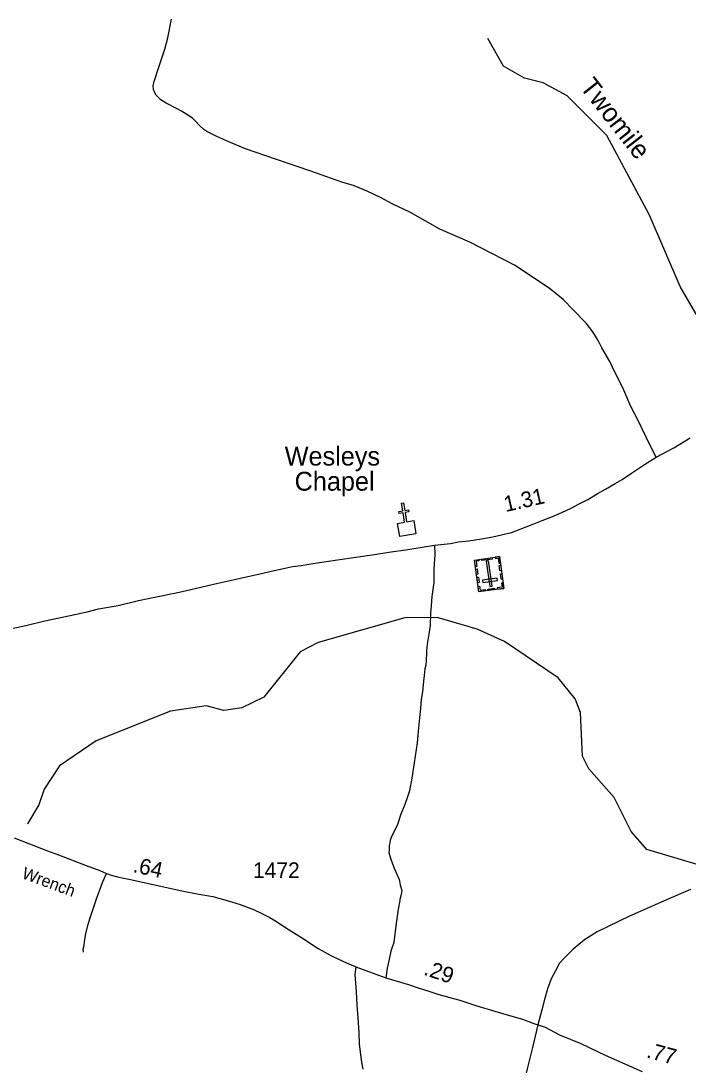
# Model space of a CAD drawing. Extents: x 2093524 to 2270757, y 289120 to 570408.
# Drawn here: x 2127083 to 2132387, y 512508 to 520807 of the extents above; entities that cross this region are included whole.
import ezdxf

# ---------------------------------------------------------------- set-up
doc = ezdxf.new("R2010")
doc.units = 0
for name, color, linetype in [('Exist Cultural Cemetery CELL', 7, 'Continuous'), ('Exist Cultural Church CELL', 7, 'Continuous'), ('Exist Cultural Church Label', 7, 'Continuous'), ('Exist Hydrographic Creek Single Shore', 7, 'Continuous'), ('Exist Hydrographic Misc Water Feature', 7, 'Continuous'), ('Exist Hydrographic Swamp Label', 7, 'Continuous'), ('Exist Road Non-System Type 51', 7, 'Continuous'), ('Exist Road Primary US Attributed', 7, 'Continuous'), ('Exist Road Primary US Mileage Hundredths English Label', 7, 'Continuous'), ('Exist Road Secondary Mileage Hundredths English Label', 7, 'Continuous'), ('Exist Road Secondary Type 51 Attributed', 7, 'Continuous'), ('Exist Road Secondary Type 51 Label', 7, 'Continuous'), ('Exist Road Secondary Type 51 Number Label', 7, 'Continuous')]:
    doc.layers.add(name, color=color, linetype=linetype)

msp = doc.modelspace()

# ---------------------------------------------------------------- linework, layer by layer
at = {"layer": 'Exist Cultural Cemetery CELL'}
for points in [[(2130921.8, 516297.1), (2130724.6, 516269.6), (2130689.4, 516521.8), (2130886.6, 516549.3)], [(2130722.2, 516526.3), (2130723.8, 516515), (2130702, 516511.9), (2130707.6, 516471.9), (2130696.6, 516470.4), (2130689.4, 516521.8)], [(2130831.3, 516530), (2130747.2, 516518.2), (2130745.7, 516529.5), (2130829.7, 516541.3)], [(2130853.8, 516544.7), (2130855.4, 516533.3), (2130877.2, 516536.3), (2130882.8, 516496.3), (2130893.8, 516497.8), (2130886.7, 516549.2)], [(2130710.7, 516451.8), (2130716.7, 516408.9), (2130705.4, 516407.3), (2130699.4, 516450.2)], [(2130809.8, 516311.1), (2130828.3, 516313.6), (2130800.2, 516514.5), (2130781.7, 516511.9)], [(2130896.3, 516480), (2130902.3, 516437.1), (2130891, 516435.6), (2130885, 516478.4)], [(2130719.8, 516386.5), (2130725.7, 516343.6), (2130714.5, 516342), (2130708.5, 516384.9)], [(2130872, 516358.9), (2130869.4, 516377.4), (2130752.8, 516361.1), (2130755.3, 516342.6)], [(2130905.6, 516413.4), (2130911.6, 516370.6), (2130900.3, 516369), (2130894.3, 516411.9)], [(2130718.5, 516312.5), (2130729.8, 516314.1), (2130734.2, 516282.2), (2130774.4, 516287.8), (2130775.9, 516276.8), (2130724.5, 516269.6)], [(2130848.4, 516286.9), (2130797.1, 516279.7), (2130795.5, 516291), (2130846.9, 516298.2)], [(2130915.8, 516340), (2130904.6, 516338.4), (2130909, 516306.5), (2130868.8, 516301), (2130870.4, 516289.9), (2130921.8, 516297.1)]]:
    msp.add_lwpolyline(points, close=True, dxfattribs=at)
at = {"layer": 'Exist Cultural Church CELL'}
msp.add_lwpolyline([(2130077.4, 516813.3), (2130133.5, 516822.8), (2130120.9, 516897.9), (2130089.3, 516892.6), (2130086.7, 516908.4), (2130118.2, 516913.7), (2130108.2, 516973), (2130124, 516975.6), (2130134, 516916.3), (2130165.6, 516921.6), (2130168.2, 516905.9), (2130136.7, 516900.6), (2130149.3, 516825.5), (2130206.2, 516835), (2130223.8, 516730), (2130095, 516708.3)], close=True, dxfattribs=at)
at = {"layer": 'Exist Hydrographic Creek Single Shore'}
msp.add_lwpolyline([(2132885.3, 513974.6), (2132951.4, 514235.7), (2133247.5, 514935.1), (2133246.4, 515309), (2133134.3, 516108.5), (2133175.3, 516274.9), (2133179.4, 517150.7), (2133069.3, 517566.2), (2132859.3, 517957.6), (2132449.4, 518480.9), (2132323.3, 518696.6), (2132079.3, 519262.4), (2131740.8, 519896), (2131425.2, 520211.8), (2131234.4, 520314.6), (2131087.6, 520351.3), (2130918.8, 520446.8), (2130794, 520667.1)], dxfattribs=at)
at = {"layer": 'Exist Hydrographic Misc Water Feature'}
msp.add_lwpolyline([(2132885.3, 513974.6), (2132059.4, 514220.8), (2131934.3, 514364.4), (2131799.4, 514636.1), (2131598.2, 514863.2), (2131548.4, 514962.6), (2131530.3, 515310.8), (2131488.3, 515419.8), (2131354.2, 515586.5), (2130927.3, 515873.9), (2130710.3, 515973.4), (2130393.3, 516065.1), (2130135.2, 516063.8), (2129445.2, 515867.7), (2129303.3, 515791.8), (2129013.1, 515433.5), (2128839.2, 515348.4), (2128697.1, 515325), (2128555.2, 515364), (2128272.3, 515320.4), (2127682.1, 515086.3), (2127391.2, 514885.4), (2127267.1, 514700.9), (2127226.1, 514577.1), (2127135.3, 514424.7)], dxfattribs=at)
at = {"layer": 'Exist Road Non-System Type 51'}
for points in [[(2132134.2, 517339.8), (2132093.8, 517416.6), (2131984.3, 517640.7), (2131932.3, 517741.8), (2131867.3, 517891.1), (2131802, 518020.4), (2131763.5, 518099.1), (2131701.7, 518208.4), (2131672.9, 518266.9), (2131630.3, 518335.8), (2131575.7, 518404.9), (2131475.8, 518506.9), (2131393.5, 518592.5), (2131283.3, 518682.7), (2131007, 518864.3), (2130652.8, 519049.4), (2130412.9, 519152.2), (2130179.5, 519282.8), (2130035, 519353.7), (2129947.9, 519401.5), (2129840.9, 519451.6), (2129725.9, 519497.9), (2129642.4, 519523.6), (2129507.4, 519570.3), (2129388.2, 519612.7), (2129271.1, 519653.1), (2129116.1, 519704.2), (2128869.8, 519789.1), (2128735, 519845.8), (2128639.8, 519887.7), (2128614.1, 519900.2), (2128562.6, 519927.3), (2128537, 519943.8), (2128505.6, 519972.4), (2128468.4, 520013.2), (2128446.8, 520033.6), (2128403.4, 520062.5), (2128359.9, 520089.3), (2128320.3, 520110.1), (2128239.2, 520153.8), (2128195.8, 520180.6), (2128158.5, 520215.4), (2128145, 520239.6), (2128137.4, 520261.8), (2128134.1, 520293.9), (2128142.7, 520325.7), (2128179, 520438.9), (2128227.8, 520581.9), (2128251.6, 520671.4), (2128280.6, 520820.8)], [(2130370.4, 516641.3), (2130372.8, 516565.3), (2130366.5, 516449.4), (2130366.4, 516343.4), (2130350.1, 516231.8), (2130344.7, 516161.9), (2130339.4, 516098), (2130335.5, 516002.1), (2130328.4, 515948.3), (2130321.5, 515900.4), (2130312.5, 515854.6), (2130307.5, 515800.7), (2130307.1, 515784.7), (2130303.9, 515724.8), (2130301.2, 515686.8), (2130294.6, 515657), (2130289.5, 515605.1), (2130282.6, 515559.2), (2130274.9, 515473.4), (2130265.7, 515413.6), (2130260.2, 515341.7), (2130250.7, 515267.9), (2130245.1, 515188), (2130232.7, 515068.3), (2130209.6, 514910.8), (2130191.1, 514787.2), (2130171.1, 514687.6), (2130156.1, 514639.9), (2130134.9, 514580.3), (2130103.4, 514503), (2130075.7, 514421.5), (2130046.5, 514358.1), (2130029.8, 514324.5), (2130019.1, 514292.7), (2130016.8, 514274.7), (2130012.6, 514264.8), (2130010.3, 514252.9), (2130011.6, 514214.8), (2130007.2, 514196.9), (2130020.3, 514152.7), (2130037.4, 514108.3), (2130050.7, 514072.1), (2130088.9, 513983.3), (2130098.1, 513941.1), (2130111.1, 513894.9), (2130106.5, 513865), (2130095.7, 513823.2), (2130095.5, 513815.2), (2130082.2, 513747.5), (2130063.5, 513613.9), (2130046.8, 513482.2), (2130034.1, 513446.5), (2130023.4, 513412.7), (2130010.2, 513349), (2130001.4, 513313.1), (2129994.8, 513279.3), (2129983.2, 513201.5)], [(2127579.6, 513405.8), (2127578, 513429.9), (2127586.6, 513457.7), (2127589.3, 513491.6), (2127600.5, 513551.4), (2127618, 513627), (2127639.4, 513694.6), (2127681.9, 513821.7), (2127730.7, 513958.7), (2127764.1, 514030.1)]]:
    msp.add_lwpolyline(points, dxfattribs=at)
at = {"layer": 'Exist Road Primary US Attributed'}
msp.add_lwpolyline([(2126923, 515960.7), (2127123.8, 516002.7), (2127272.5, 516037.7), (2127437.2, 516072.4), (2127610, 516110.9), (2127700.4, 516133.1), (2127856.9, 516159.9), (2128017.7, 516200.7), (2128096, 516215.1), (2128186.4, 516235.3), (2128260.7, 516249.8), (2128316.9, 516262.7), (2128423.4, 516284.5), (2128614.3, 516330.7), (2128781, 516367.3), (2128911.6, 516396.7), (2128995.9, 516415), (2129072.3, 516433.5), (2129170.7, 516455.5), (2129243, 516470), (2129311.2, 516478.6), (2129371.4, 516489.4), (2129423.6, 516498.4), (2129600.1, 516524.8), (2129746.5, 516545.9), (2129894.9, 516566.9), (2130007.3, 516584.6), (2130159.7, 516605.6), (2130272, 516623.3), (2130370.4, 516641.3), (2130498.6, 516654.7), (2130562.8, 516665.5), (2130645, 516675.8), (2130745.3, 516689.8), (2130835.6, 516706), (2130984.3, 516741), (2131133.4, 516798), (2131226.2, 516836.1), (2131308.8, 516868.4), (2131383.4, 516898.9), (2131458.2, 516935.4), (2131520.8, 516968.2), (2131589.5, 517002.8), (2131664.4, 517047.3), (2131729.2, 517085.9), (2131806, 517130.4), (2131862.7, 517163.3), (2131937.7, 517213.7), (2132041.1, 517281.7), (2132134.2, 517339.8), (2132223.2, 517388), (2132273.7, 517415), (2132403.3, 517492.3)], dxfattribs=at)
at = {"layer": 'Exist Road Secondary Type 51 Attributed'}
for points in [[(2127029.9, 514314.8), (2127152.9, 514266.3), (2127295.8, 514211.4), (2127381.1, 514179.7), (2127603.4, 514095.3), (2127710.6, 514055.1), (2127764.1, 514030.1), (2127799.8, 514017.3), (2127851.6, 514004.3), (2127901.3, 513993.3), (2127955.1, 513982.2), (2128134.3, 513942.6), (2128361.3, 513894.1), (2128498.7, 513865.3), (2128608.4, 513849.1), (2128723.7, 513816.8), (2128827.1, 513784.7), (2128932.2, 513744.6), (2128997.6, 513713.3), (2129061, 513682), (2129102.5, 513657.2), (2129155.7, 513622.1), (2129215, 513582.9), (2129313.7, 513521), (2129445.9, 513434.3), (2129552.8, 513376.2), (2129608.2, 513351), (2129671.6, 513319.8), (2129745, 513288.3)], [(2132407.1, 513904.7), (2132233.6, 513828.2), (2131920.8, 513690.5), (2131664.4, 513567.7), (2131563.1, 513503.7), (2131473.6, 513429.5), (2131402.2, 513357), (2131365.4, 513317.7), (2131332.2, 513256.4), (2131298.9, 513193.1), (2131269.3, 513113.7), (2131245.6, 513030.2), (2131224, 512948.6), (2131193.5, 512827.2)], [(2129745, 513288.3), (2129737.8, 513228.5), (2129747, 513090.3), (2129752.9, 512984.2), (2129760.8, 512884), (2129768.5, 512765.9), (2129772.6, 512675.8), (2129783, 512591.6), (2129791.7, 512531.5), (2129800.6, 512475.3)], [(2129745, 513288.3), (2129983.2, 513201.5), (2130172.1, 513145.7), (2130241.6, 513122.3), (2130325.1, 513096.7), (2130406.5, 513069), (2130494, 513045.3), (2130573.6, 513023.7), (2130700.7, 512983.1), (2130877.6, 512929.6), (2130987, 512897.4), (2131070.5, 512873.7), (2131134, 512848.4), (2131153.9, 512842), (2131193.5, 512827.2)], [(2131193.5, 512827.2), (2131150, 512648.1), (2131108.6, 512479), (2131062.6, 512283.9), (2131010.3, 512069), (2130964.3, 511870), (2130903.1, 511611.2), (2130848.4, 511378.4), (2130789.2, 511117.6), (2130743.3, 510924.5), (2130710.2, 510771.2), (2130672.7, 510596)], [(2131193.5, 512827.2), (2131251.2, 512810.1), (2131365.9, 512747.8), (2131534.6, 512680.4), (2131728.7, 512586.5), (2132022, 512456.6)]]:
    msp.add_lwpolyline(points, dxfattribs=at)

# ---------------------------------------------------------------- texts
at = {"layer": 'Exist Cultural Church Label'}
for s, p in [('Wesleys', (2129180.3, 517272.8)), ('Chapel', (2129259.1, 517073.2))]:
    msp.add_text(s, height=150, dxfattribs=at).set_placement(p)
at = {"layer": 'Exist Hydrographic Swamp Label'}
msp.add_text('Twomile', height=150, rotation=308.07186, dxfattribs=at).set_placement((2131520.1, 520280.3))
at = {"layer": 'Exist Road Primary US Mileage Hundredths English Label'}
msp.add_text('1.31', height=125, rotation=12.68645, dxfattribs=at).set_placement((2130937.5, 516903.2))
at = {"layer": 'Exist Road Secondary Mileage Hundredths English Label'}
for s, rotation, p in [('.64', 347.53896, (2127968.2, 514043.3)), ('.29', 341.20694, (2130278.6, 513228)), ('.77', 344.87343, (2132049.6, 512570.2))]:
    msp.add_text(s, height=125, rotation=rotation, dxfattribs=at).set_placement(p)
at = {"layer": 'Exist Road Secondary Type 51 Label'}
msp.add_text('Wrench', height=95, rotation=339.61222, dxfattribs=at).set_placement((2127084.3, 513996))
at = {"layer": 'Exist Road Secondary Type 51 Number Label'}
msp.add_text('1472', height=125, dxfattribs=at).set_placement((2128927.9, 513994.3))

doc.saveas('drawing.dxf')
